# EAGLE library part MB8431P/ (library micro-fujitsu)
MICROCONTROLLER/MEMORY DEVICE
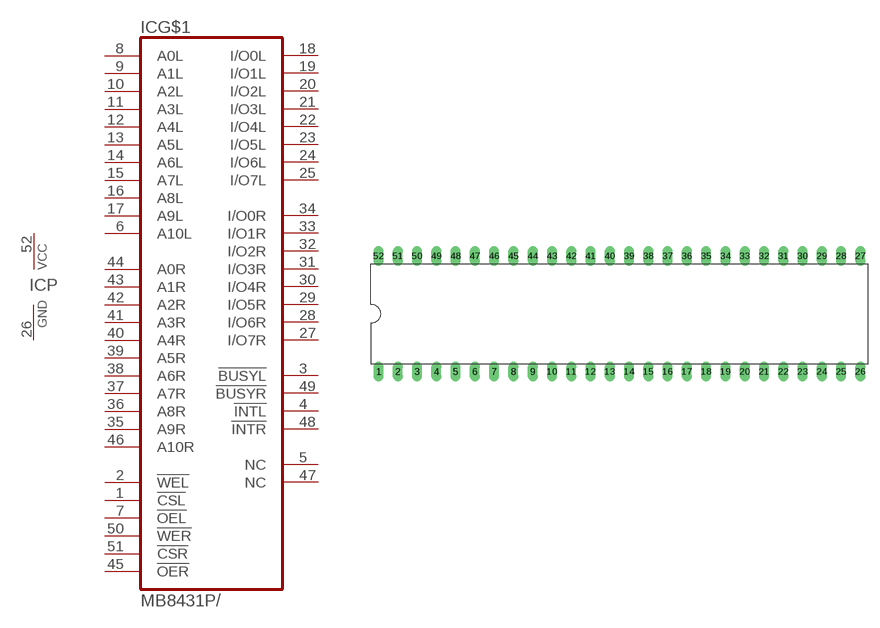
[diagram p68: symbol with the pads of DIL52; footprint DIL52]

Designator prefix IC; gates G$1=MB8431P/ P=VCC-GND

## MB8431P/ (OC_FARNELL: unknown; OC_NEWARK: unknown)  [DIL52]
1  G$1:!CSL  in
2  G$1:!WEL  in
3  G$1:!BUSYL  out
4  G$1:!INTL  out
5  G$1:NC  nc
6  G$1:A10L  in
7  G$1:!OEL  in
8  G$1:A0L  in
9  G$1:A1L  in
10  G$1:A2L  in
11  G$1:A3L  in
12  G$1:A4L  in
13  G$1:A5L  in
14  G$1:A6L  in
15  G$1:A7L  in
16  G$1:A8L  in
17  G$1:A9L  in
18  G$1:I/O0L
19  G$1:I/O1L
20  G$1:I/O2L
21  G$1:I/O3L
22  G$1:I/O4L
23  G$1:I/O5L
24  G$1:I/O6L
25  G$1:I/O7L
26  P:GND  pwr
27  G$1:I/O7R
28  G$1:I/O6R
29  G$1:I/O5R
30  G$1:I/O4R
31  G$1:I/O3R
32  G$1:I/O2R
33  G$1:I/O1R
34  G$1:I/O0R
35  G$1:A9R  in
36  G$1:A8R  in
37  G$1:A7R  in
38  G$1:A6R  in
39  G$1:A5R  in
40  G$1:A4R  in
41  G$1:A3R  in
42  G$1:A2R  in
43  G$1:A1R  in
44  G$1:A0R  in
45  G$1:!OER  in
46  G$1:A10R  in
47  G$1:NC  nc
48  G$1:!INTR  out
49  G$1:!BUSYR  out
50  G$1:!WER  in
51  G$1:!CSR  in
52  P:VCC  pwr

## Footprint DIL52 (pad centres in mm)
Dual In Line Package
drill 0.813 long: 1 -31.75,-7.62; 2 -29.21,-7.62; 3 -26.67,-7.62; 4 -24.13,-7.62; 5 -21.59,-7.62; 6 -19.05,-7.62; 7 -16.51,-7.62; 8 -13.97,-7.62; 9 -11.43,-7.62; 10 -8.89,-7.62; 11 -6.35,-7.62; 12 -3.81,-7.62; 13 -1.27,-7.62; 14 1.27,-7.62; 15 3.81,-7.62; 16 6.35,-7.62; 17 8.89,-7.62; 18 11.43,-7.62; 19 13.97,-7.62; 20 16.51,-7.62; 21 19.05,-7.62; 22 21.59,-7.62; 23 24.13,-7.62; 24 26.67,-7.62; 25 29.21,-7.62; 26 31.75,-7.62; 27 31.75,7.62; 28 29.21,7.62; 29 26.67,7.62; 30 24.13,7.62; 31 21.59,7.62; 32 19.05,7.62; 33 16.51,7.62; 34 13.97,7.62; 35 11.43,7.62; 36 8.89,7.62; 37 6.35,7.62; 38 3.81,7.62; 39 1.27,7.62; 40 -1.27,7.62; 41 -3.81,7.62; 42 -6.35,7.62; 43 -8.89,7.62; 44 -11.43,7.62; 45 -13.97,7.62; 46 -16.51,7.62; 47 -19.05,7.62; 48 -21.59,7.62; 49 -24.13,7.62; 50 -26.67,7.62; 51 -29.21,7.62; 52 -31.75,7.62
